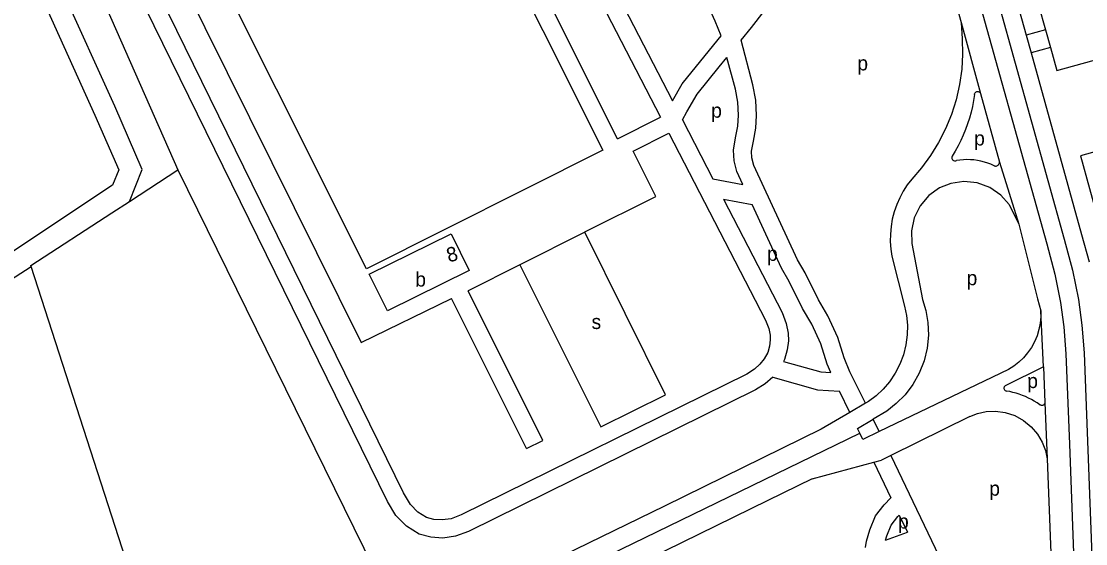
# Model space of a CAD drawing. Extents: x 158358 to 160383, y 379531 to 380764.
# Drawn here: x 159216.2 to 159510.8, y 379916.8 to 380061.3 of the extents above; entities that cross this region are included whole.
import ezdxf

# ---------------------------------------------------------------- set-up
doc = ezdxf.new("R2010")
doc.units = 0
for name, color, linetype in [('BLT_Basislijn', 7, 'Continuous'), ('BLT_Bebouwing', 7, 'Continuous'), ('BLT_Centroide', 7, 'Continuous'), ('BLT_Huisnummer', 7, 'Continuous'), ('BLT_Vlakafsluiter', 7, 'Continuous')]:
    doc.layers.add(name, color=color, linetype=linetype)

msp = doc.modelspace()

# ---------------------------------------------------------------- linework, layer by layer
at = {"layer": 'BLT_Basislijn'}
for p, q in [((159210.62, 380131.18), (159259.52, 380020.21)), ((159499.64, 380058.95), (159494.29, 380057.47)), ((159500.98, 380054.13), (159495.63, 380052.65)), ((159481.66, 380041.36), (159486.86, 380022.39)), ((159246.18, 380011.53), (159259.52, 380020.21)), ((159259.52, 380020.21), (159319.52, 379898.27)), ((159407.62, 380017.72), (159415.89, 380016.22)), ((159241.26, 380008.34), (159246.18, 380011.53)), ((159410.52, 380012.11), (159418.45, 380010.68)), ((159489.54, 380010.69), (159492.22, 380005.25)), ((159492.22, 380005.25), (159497.38, 379984.59)), ((159372.17, 380003), (159354.22, 379994.01)), ((159462.68, 379999.92), (159465.62, 379984.42)), ((159457.11, 379996.35), (159460.63, 379982.52)), ((159354.22, 379994.01), (159339.86, 379986.77)), ((159360.52, 379945.35), (159339.86, 379986.77)), ((159356.05, 379943.12), (159335.31, 379984.69)), ((159497.38, 379984.59), (159498.3, 379981.28)), ((159499.11, 379965.74), (159488.48, 379960.53)), ((159499.11, 379965.74), (159499.43, 379955.88)), ((159449.79, 379955.67), (159445.47, 379953.12)), ((159450.66, 379956.19), (159449.79, 379955.67)), ((159445.47, 379953.12), (159437.6, 379948.48)), ((159478.71, 379952.01), (159456.82, 379941.22)), ((159437.6, 379948.48), (159394.17, 379927.2)), ((159356.05, 379943.12), (159360.52, 379945.35)), ((159435.11, 379934.82), (159452.15, 379939.39)), ((159452.15, 379939.39), (159454.25, 379939.95)), ((159456.82, 379941.22), (159454.25, 379939.95)), ((159435.11, 379934.82), (159422.78, 379928.74)), ((159422.78, 379928.74), (159380.52, 379908.13)), ((159394.17, 379927.2), (159322.57, 379892.39))]:
    msp.add_line(p, q, dxfattribs=at)
for points in [[(159246.18, 380011.53), (159249.72, 380020.35), (159242.08, 380037.85), (159212.76, 380102.49), (159171.52, 380192.1), (159165.17, 380205.1)], [(159409.9, 380057.28), (159408.24, 380061.34), (159405.21, 380068.18), (159402.09, 380074.3), (159399.21, 380079.03), (159396.05, 380083.92), (159392.79, 380088.8), (159389.65, 380094.46), (159384.11, 380106.67), (159380.62, 380114.96), (159377.78, 380122.09), (159375.17, 380127.61), (159369.42, 380138.21), (159364.61, 380147.03), (159360.96, 380154.13), (159357.4, 380161.87), (159351.39, 380173.87), (159347.68, 380181.46), (159344.72, 380187.95), (159341.7, 380196.64), (159338.93, 380203.49), (159338.57, 380204.27)], [(159319.93, 380178.01), (159321.73, 380177.36), (159325.18, 380174.93), (159327.91, 380171.76), (159396.43, 380039.34)], [(159266.43, 380151.83), (159307.04, 380172.17), (159310.81, 380173.55), (159313.93, 380174.01), (159316.77, 380173.82), (159319.41, 380172.88), (159321.79, 380171.2), (159323.74, 380168.94), (159393.11, 380034.87)], [(159424.15, 379962.9), (159422.07, 379961.1), (159419.42, 379959.39), (159339.93, 379920.21), (159336.41, 379918.87), (159332.9, 379918.38), (159329.52, 379918.6), (159326.34, 379919.46), (159322.82, 379921.64), (159319.91, 379924.62), (159317.59, 379928.49), (159224.33, 380118.68), (159223.12, 380122.52), (159222.7, 380126.41), (159223.18, 380129.99), (159224.73, 380133.69), (159227.11, 380136.76), (159230.07, 380139.21), (159234.05, 380141.22), (159259.74, 380154.08)], [(159381.2, 380028.82), (159327.43, 380136.39), (159314.14, 380129.8)], [(159395.41, 380030.43), (159422.18, 379978.7), (159423.08, 379976.36), (159423.44, 379974.53), (159423.48, 379973.22), (159423.24, 379971.45), (159422.76, 379969.71), (159421.82, 379967.99), (159420.63, 379966.46), (159419.07, 379965.11), (159416.95, 379963.75), (159337.94, 379924.8), (159335.17, 379923.75), (159332.71, 379923.41), (159330.35, 379923.55), (159328.36, 379924.1), (159325.97, 379925.57), (159323.89, 379927.7), (159321.98, 379930.88), (159228.98, 380120.55)], [(159202.17, 380111.15), (159207.31, 380100), (159236.59, 380035.42), (159243.21, 380020.25), (159241.51, 380016), (159185.59, 379978.81), (159141.72, 379949.29)], [(159415.39, 380056.09), (159418.29, 380059.65), (159450.22, 380100.85), (159452.38, 380102.89), (159454.86, 380104.24), (159463.46, 380107.02)], [(159463.46, 380107.02), (159476.27, 380061.01)], [(159250.47, 380098.02), (159248.49, 380097.03), (159310.29, 379972.49), (159335.31, 379984.69)], [(159487, 380083.63), (159494.29, 380057.47)], [(159480.25, 380081.76), (159479.66, 380081.5), (159479.13, 380081.14), (159478.7, 380080.71), (159478.45, 380080.34), (159478.18, 380079.79), (159478.09, 380079.28), (159478.05, 380078.78), (159478.17, 380078.06), (159500, 379999.75), (159502.26, 379991.38), (159503.81, 379983.58), (159504.71, 379976.78), (159505.3, 379969.31), (159506.3, 379944.33)], [(159482.18, 380082.29), (159504.82, 380001.07), (159507.13, 379992.52), (159508.75, 379984.4), (159509.68, 379977.31), (159510.29, 379969.61)], [(159476.27, 380061.01), (159476.61, 380056.47), (159476.7, 380052.29), (159476.45, 380048.06), (159475.85, 380043.84), (159474.9, 380039.65), (159473.6, 380035.55), (159471.97, 380031.58), (159470.03, 380027.78), (159467.81, 380024.18), (159465.32, 380020.81), (159462.62, 380017.7)], [(159396.43, 380039.34), (159399.1, 380044.03), (159405.49, 380051.88), (159409.9, 380057.28)], [(159494.29, 380057.47), (159495.63, 380052.65)], [(159449.79, 379955.67), (159445.52, 379964.4), (159443.89, 379968.26), (159442.14, 379973.9), (159439.39, 379979.89), (159436.81, 379984.26), (159433.11, 379991.77), (159431.04, 379995.35), (159418.96, 380021.49), (159418.41, 380023.54), (159418.31, 380025.43), (159418.79, 380028.17), (159419.49, 380031.74), (159419.66, 380035.31), (159419.52, 380039.55), (159418.68, 380043.75), (159415.39, 380056.09)], [(159399.16, 380034.06), (159400.43, 380036.28), (159403.24, 380041.2), (159409.36, 380048.72), (159411.48, 380051.31)], [(159415.89, 380016.22), (159414.24, 380019.78), (159413.44, 380022.75), (159413.29, 380025.74), (159413.88, 380029.08), (159414.51, 380032.34), (159414.66, 380035.35), (159414.54, 380038.97), (159413.81, 380042.61), (159411.48, 380051.31)], [(159495.63, 380052.65), (159509.64, 380002.4), (159511.69, 379994.82)], [(159480, 380041.06), (159479.74, 380039.43), (159479.41, 380037.8), (159479.02, 380036.18), (159478.58, 380034.58), (159478.06, 380032.99), (159477.49, 380031.43), (159476.86, 380029.88), (159476.18, 380028.36), (159475.43, 380026.88), (159474.64, 380025.42), (159473.79, 380024)], [(159480, 380041.06), (159480.03, 380041.26), (159480.11, 380041.47), (159480.24, 380041.65), (159480.41, 380041.79), (159480.6, 380041.88), (159480.8, 380041.91), (159481.02, 380041.9), (159481.23, 380041.83), (159481.41, 380041.7), (159481.56, 380041.54), (159481.66, 380041.36)], [(159381.2, 380028.82), (159393.11, 380034.87)], [(159399.16, 380034.06), (159407.62, 380017.72)], [(159385.51, 380025.4), (159395.41, 380030.43)], [(159372.17, 380003), (159372.12, 380003.1), (159391.77, 380012.88), (159385.51, 380025.4)], [(159473.79, 380024), (159473.72, 380023.82), (159473.7, 380023.62), (159473.72, 380023.41), (159473.79, 380023.21), (159473.9, 380023.05), (159474.04, 380022.91), (159474.21, 380022.81), (159474.41, 380022.74), (159474.62, 380022.72), (159474.82, 380022.75), (159475, 380022.82)], [(159485.43, 380021.4), (159484.55, 380021.79), (159483.65, 380022.13), (159482.72, 380022.42), (159481.77, 380022.66), (159480.81, 380022.85), (159479.84, 380022.98), (159478.86, 380023.06), (159477.89, 380023.08), (159476.92, 380023.05), (159475.95, 380022.96), (159475, 380022.82)], [(159485.43, 380021.4), (159485.58, 380021.34), (159485.76, 380021.31), (159485.95, 380021.31), (159486.15, 380021.35), (159486.34, 380021.43), (159486.51, 380021.55), (159486.66, 380021.7), (159486.76, 380021.87), (159486.83, 380022.05), (159486.86, 380022.23), (159486.86, 380022.39)], [(159462.62, 380017.7), (159461.4, 380016.09), (159460.28, 380014.37), (159459.3, 380012.55), (159458.46, 380010.63), (159457.77, 380008.65), (159457.25, 380006.61), (159456.89, 380004.55), (159456.7, 380002.47), (159456.68, 380000.39), (159456.82, 379998.35), (159457.11, 379996.35)], [(159489.54, 380010.69), (159487.23, 380013.28), (159484.21, 380015.36), (159480.7, 380016.65), (159476.99, 380017.03), (159473.45, 380016.51), (159470.28, 380015.24), (159467.36, 380013.17), (159464.95, 380010.34), (159463.3, 380006.97), (159462.55, 380003.39), (159462.68, 379999.92)], [(159410.52, 380012.11), (159426.74, 379980.75), (159427.91, 379977.74), (159428.42, 379975.08), (159428.49, 379972.96), (159428.15, 379970.46), (159427.43, 379967.82), (159427.12, 379967.26)], [(159440.19, 379964.18), (159439.19, 379966.54), (159437.46, 379972.11), (159434.96, 379977.57), (159432.41, 379981.88), (159428.7, 379989.41), (159426.59, 379993.05), (159418.45, 380010.68)], [(159218.86, 379993.76), (159241.26, 380008.34)], [(159354.22, 379994.01), (159376.57, 379949.17), (159394.51, 379958.01), (159372.17, 380003)], [(159163.13, 379957.51), (159218.93, 379993.53)], [(159218.93, 379993.53), (159218.86, 379993.76)], [(159267.43, 379843.69), (159218.93, 379993.53)], [(159465.62, 379984.42), (159466.55, 379981.31), (159467.1, 379977.98), (159467.22, 379974.5), (159466.87, 379970.95), (159466.03, 379967.43), (159464.71, 379964.05), (159462.95, 379960.89), (159460.8, 379958.05), (159458.35, 379955.57), (159455.69, 379953.49), (159451.94, 379951.26)], [(159460.63, 379982.52), (159461.16, 379979.97), (159461.41, 379977.31), (159461.36, 379974.57), (159461, 379971.81), (159460.32, 379969.09), (159459.32, 379966.45), (159458.03, 379963.96), (159456.47, 379961.65), (159454.69, 379959.57), (159452.74, 379957.75), (159450.66, 379956.19)], [(159498.3, 379981.28), (159498.32, 379979.58), (159498.16, 379977.84), (159497.82, 379976.1), (159497.3, 379974.37), (159496.6, 379972.7), (159495.72, 379971.11), (159494.69, 379969.61), (159493.51, 379968.25), (159492.22, 379967.03), (159490.84, 379965.96), (159489.4, 379965.06)], [(159510.29, 379969.61), (159513.9, 379874.36), (159515.76, 379825.72)], [(159427.12, 379967.26), (159437.44, 379964.38), (159440.19, 379964.18)], [(159424.15, 379962.9), (159436.58, 379959.43), (159442.6, 379958.99)], [(159489.4, 379965.06), (159453.61, 379947.84)], [(159488.48, 379960.53), (159488.35, 379960.42), (159488.24, 379960.27), (159488.16, 379960.11), (159488.13, 379959.93), (159488.13, 379959.75), (159488.17, 379959.59), (159488.25, 379959.43), (159488.37, 379959.29), (159488.51, 379959.17), (159488.67, 379959.1), (159488.84, 379959.06)], [(159445.47, 379953.12), (159442.6, 379958.99)], [(159498.06, 379955.29), (159497.3, 379955.8), (159496.53, 379956.27), (159495.73, 379956.72), (159494.91, 379957.13), (159494.08, 379957.51), (159493.23, 379957.86), (159492.37, 379958.17), (159491.5, 379958.45), (159490.62, 379958.69), (159489.73, 379958.89), (159488.84, 379959.06)], [(159499.43, 379955.88), (159499.41, 379955.71), (159499.36, 379955.55), (159499.27, 379955.39), (159499.15, 379955.26), (159499.01, 379955.17), (159498.86, 379955.1), (159498.69, 379955.07), (159498.52, 379955.07), (159498.34, 379955.11), (159498.19, 379955.19), (159498.06, 379955.29)], [(159448.26, 379947.41), (159447.62, 379948.7), (159451.94, 379951.26)], [(159453.61, 379947.84), (159451.94, 379951.26)], [(159478.71, 379952.01), (159480.85, 379952.85), (159483.24, 379953.37), (159485.82, 379953.49), (159488.5, 379953.13), (159491.13, 379952.28), (159493.58, 379950.94), (159495.71, 379949.19), (159497.45, 379947.13), (159498.75, 379944.89), (159499.6, 379942.59), (159500.05, 379940.35)], [(159453.61, 379947.84), (159449.11, 379945.67), (159448.26, 379947.41)], [(159325.44, 379760.34), (159321.72, 379768.09), (159291.12, 379830.62), (159289.02, 379835.49), (159287.78, 379839.95), (159287.26, 379844.3), (159287.26, 379849.47), (159288.22, 379854), (159289.89, 379858.72), (159291.65, 379862.09), (159294.39, 379866.21), (159297.06, 379869.48), (159299.52, 379871.84), (159302.19, 379874.04), (159306.6, 379877.33), (159316.34, 379883.36), (159448.26, 379947.41)], [(159506.3, 379944.33), (159508.9, 379874.17), (159510.76, 379825.54)], [(159452.15, 379939.39), (159456.87, 379929.53)], [(159456.82, 379941.22), (159501.74, 379847.38), (159503.21, 379843.58), (159503.96, 379840.8)], [(159500.05, 379940.35), (159503.96, 379840.8)], [(159449.87, 379915.82), (159450.07, 379917.49), (159450.98, 379920.68), (159452.59, 379924.52), (159454.98, 379927.6), (159456.87, 379929.53)], [(159455.37, 379917.84), (159455.71, 379919.02), (159456.94, 379921.98), (159458.76, 379924.31), (159459.17, 379924.73)], [(159459.17, 379924.73), (159461.41, 379920.05)], [(159455.37, 379917.84), (159461.41, 379920.05)]]:
    msp.add_lwpolyline(points, dxfattribs=at)
msp.add_lwpolyline([(159327.32, 380125.11), (159377.14, 380025.65), (159311.79, 379992.91), (159261.97, 380092.37)], close=True, dxfattribs=at)
at = {"layer": 'BLT_Bebouwing'}
for points in [[(159553.96, 380081.41), (159497.74, 380065.78), (159499.64, 380058.95)], [(159499.64, 380058.95), (159500.98, 380054.13)], [(159500.98, 380054.13), (159502.77, 380047.7), (159539.2, 380057.83), (159545.72, 380034.27), (159509.29, 380024.15), (159514.34, 380006.08), (159528.58, 380010.05), (159570.56, 380021.72)]]:
    msp.add_lwpolyline(points, dxfattribs=at)
msp.add_lwpolyline([(159312.53, 379991.42), (159335.2, 380002.58), (159340.18, 379992.44), (159317.52, 379981.29)], close=True, dxfattribs=at)
at = {"layer": 'BLT_Vlakafsluiter'}
for p, q in [((159476.27, 380061.01), (159481.66, 380041.36)), ((159486.86, 380022.39), (159492.22, 380005.25)), ((159499.11, 379965.74), (159498.3, 379981.28)), ((159499.43, 379955.88), (159500.05, 379940.35))]:
    msp.add_line(p, q, dxfattribs=at)

# ---------------------------------------------------------------- texts
at = {"layer": 'BLT_Centroide'}
for s, p in [('p', (159447.56, 380047.76)), ('p', (159407.11, 380034.68)), ('p', (159479.87, 380026.98)), ('p', (159422.56, 379995.07)), ('b', (159325.23, 379987.97)), ('p', (159477.8, 379988.34)), ('s', (159374.02, 379976.22)), ('p', (159494.57, 379959.88)), ('p', (159484.06, 379930.11)), ('p', (159458.82, 379921.01))]:
    msp.add_text(s, height=4, dxfattribs=at).set_placement(p)
at = {"layer": 'BLT_Huisnummer'}
msp.add_text('8', height=4, rotation=15.5338, dxfattribs=at).set_placement((159334.52, 379994.6))

doc.saveas('drawing.dxf')
